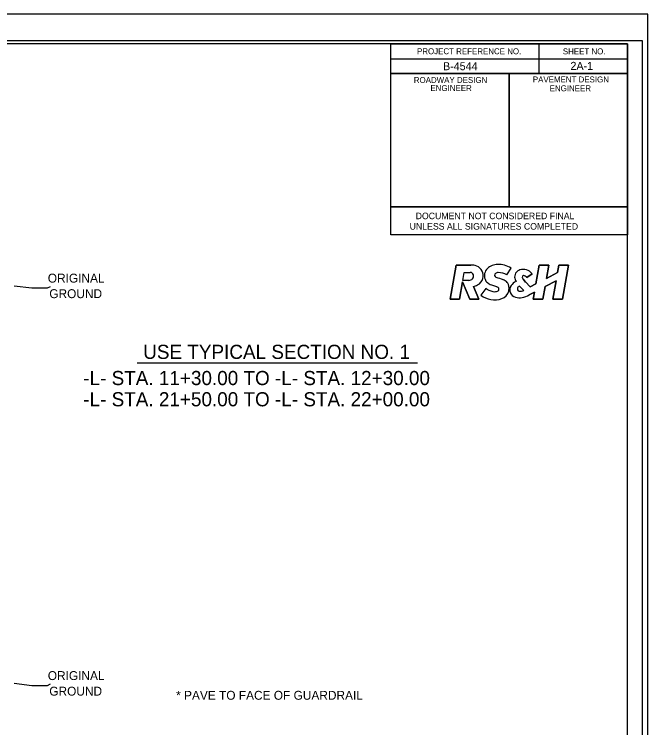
# Model space of a CAD drawing. Extents: x 60664 to 60833, y 51234 to 51344.
# Drawn here: x 60779.3 to 60832.8, y 51284.2 to 51344.4 of the extents above; entities that cross this region are included whole.
import ezdxf

# ---------------------------------------------------------------- set-up
doc = ezdxf.new("R2010")
doc.units = 0
for name, color, linetype in [('Default', 7, 'Continuous'), ('Prop Dimension Text', 7, 'Continuous'), ('Prop DSN Text', 7, 'Continuous'), ('Sheet Cutting Line CELL', 7, 'Continuous'), ('Sheet Data Field CELL', 7, 'Continuous'), ('Sheet Plot Border Inside CELL', 7, 'Continuous'), ('Sheet Plot Border Outside CELL', 7, 'Continuous'), ('Sheet Typical CELL', 7, 'Continuous'), ('Typical Slope Point Local CELL', 7, 'Continuous'), ('Typical Text Label CELL', 7, 'Continuous')]:
    doc.layers.add(name, color=color, linetype=linetype)

msp = doc.modelspace()

# ---------------------------------------------------------------- linework, layer by layer
at = {"layer": 'Default'}
for p, q in [((60816.122, 51320.369), (60816.63, 51323.249)), ((60816.63, 51323.249), (60816.122, 51320.369)), ((60816.63, 51323.249), (60817.88, 51323.249)), ((60817.88, 51323.249), (60816.63, 51323.249)), ((60823.383, 51321.661), (60823.659, 51323.25)), ((60823.659, 51323.25), (60823.383, 51321.661)), ((60823.659, 51323.25), (60824.471, 51323.25)), ((60824.471, 51323.25), (60823.659, 51323.25)), ((60824.471, 51323.25), (60824.273, 51322.128)), ((60824.273, 51322.128), (60824.471, 51323.25)), ((60825.2, 51322.624), (60825.312, 51323.248)), ((60825.312, 51323.248), (60825.2, 51322.624)), ((60825.312, 51323.248), (60826.119, 51323.248)), ((60826.119, 51323.248), (60825.312, 51323.248)), ((60826.119, 51323.248), (60825.616, 51320.364)), ((60825.616, 51320.364), (60826.119, 51323.248)), ((60817.212, 51321.952), (60817.33, 51322.631)), ((60817.212, 51321.952), (60817.33, 51322.631)), ((60817.33, 51322.631), (60817.836, 51322.631)), ((60817.33, 51322.631), (60817.836, 51322.631)), ((60820.918, 51322.42), (60821.28, 51322.999)), ((60824.273, 51322.128), (60825.2, 51322.624)), ((60825.2, 51322.624), (60824.273, 51322.128)), ((60822.323, 51322.03), (60822.511, 51321.814)), ((60822.511, 51321.814), (60822.323, 51322.03)), ((60823.058, 51322.521), (60822.62, 51322.185)), ((60822.62, 51322.185), (60823.058, 51322.521)), ((60817.187, 51321.821), (60816.928, 51320.369)), ((60816.928, 51320.369), (60817.187, 51321.821)), ((60817.789, 51320.363), (60817.187, 51321.821)), ((60817.187, 51321.821), (60817.789, 51320.363)), ((60817.719, 51321.952), (60817.212, 51321.952)), ((60817.719, 51321.952), (60817.212, 51321.952)), ((60818.119, 51321.436), (60818.556, 51320.363)), ((60818.556, 51320.363), (60818.119, 51321.436)), ((60819.615, 51321.577), (60820.058, 51321.426)), ((60822.354, 51321.109), (60821.996, 51321.48)), ((60821.996, 51321.48), (60822.354, 51321.109)), ((60822.506, 51321.821), (60822.896, 51321.408)), ((60822.511, 51321.814), (60822.506, 51321.821)), ((60822.896, 51321.408), (60822.506, 51321.821)), ((60822.506, 51321.821), (60822.511, 51321.814)), ((60822.896, 51321.408), (60823.383, 51321.661)), ((60823.383, 51321.661), (60822.896, 51321.408)), ((60824.149, 51321.44), (60823.963, 51320.364)), ((60823.963, 51320.364), (60824.149, 51321.44)), ((60825.079, 51321.926), (60824.149, 51321.44)), ((60824.149, 51321.44), (60825.079, 51321.926)), ((60824.797, 51320.364), (60825.079, 51321.926)), ((60825.079, 51321.926), (60824.797, 51320.364)), ((60819.148, 51321.267), (60818.717, 51320.707)), ((60819.246, 51321.206), (60819.148, 51321.267)), ((60823.256, 51320.967), (60822.805, 51320.729)), ((60822.805, 51320.729), (60823.256, 51320.967)), ((60823.145, 51320.364), (60823.256, 51320.967)), ((60823.256, 51320.967), (60823.145, 51320.364)), ((60816.928, 51320.369), (60816.122, 51320.369)), ((60816.122, 51320.369), (60816.928, 51320.369)), ((60818.556, 51320.363), (60817.789, 51320.363)), ((60817.789, 51320.363), (60818.556, 51320.363)), ((60823.963, 51320.364), (60823.145, 51320.364)), ((60823.145, 51320.364), (60823.963, 51320.364)), ((60825.616, 51320.364), (60824.797, 51320.364)), ((60824.797, 51320.364), (60825.616, 51320.364))]:
    msp.add_line(p, q, dxfattribs=at)
for centre, radius, start, end in [((60817.88, 51321.816), 1.433, 69.69485, 90), ((60817.88, 51321.816), 1.433, 69.69485, 90), ((60820.164, 51321.865), 1.433, 91.16743, 110.05168), ((60820.179, 51321.123), 2.175, 59.57473, 91.16743), ((60817.836, 51322.365), 0.266, 12.5709, 90), ((60817.836, 51322.365), 0.266, 12.5709, 90), ((60818.082, 51322.361), 0.851, 344.02211, 69.69485), ((60818.082, 51322.361), 0.851, 344.02211, 69.69485), ((60819.89, 51322.349), 0.865, 134.98186, 200.37403), ((60820.043, 51322.196), 1.081, 110.05138, 134.98186), ((60822.14, 51322.271), 0.561, 136.15701, 184.32839), ((60822.14, 51322.271), 0.561, 136.15701, 184.32839), ((60822.222, 51322.192), 0.674, 108.31914, 136.15701), ((60822.222, 51322.192), 0.674, 108.31914, 136.15701), ((60822.311, 51321.924), 0.957, 38.60783, 108.31914), ((60822.311, 51321.924), 0.957, 38.60783, 108.31914), ((60817.719, 51322.338), 0.387, 270, 12.5711), ((60817.719, 51322.338), 0.387, 270, 12.5711), ((60818.021, 51322.379), 0.914, 297.83786, 344.02211), ((60818.021, 51322.379), 0.914, 297.83786, 344.02211), ((60819.707, 51322.28), 0.669, 200.37403, 230.33767), ((60820.061, 51322.402), 0.175, 124.86909, 249.8559), ((60820.193, 51322.213), 0.405, 88.99469, 124.86909), ((60843.623, 51386.635), 68.593, 249.8559, 250.3798), ((60820.174, 51321.123), 1.495, 60.14955, 88.99469), ((60820.301, 51321.213), 0.861, 40.11805, 70.3798), ((60822.434, 51322.293), 0.856, 184.32839, 211.12165), ((60822.434, 51322.293), 0.856, 184.32839, 211.12165), ((60822.361, 51322.226), 0.14, 186.40063, 205.48341), ((60822.361, 51322.226), 0.14, 186.40063, 205.48341), ((60822.777, 51322.424), 0.601, 205.48341, 221.01883), ((60822.777, 51322.424), 0.601, 205.48341, 221.01883), ((60817.613, 51323.152), 1.789, 286.42537, 297.83787), ((60817.613, 51323.152), 1.789, 286.42537, 297.83786), ((60819.961, 51322.587), 1.067, 230.33768, 251.11286), ((60819.908, 51320.986), 0.464, 52.70165, 70.6731), ((60820.547, 51321.421), 0.54, 15.06796, 40.11805), ((60819.947, 51321.259), 1.162, 360, 15.06796), ((60821.827, 51321.16), 0.652, 147.36254, 253.36188), ((60821.827, 51321.16), 0.652, 147.36254, 253.36188), ((60821.991, 51321.055), 0.847, 110.00398, 147.36284), ((60821.991, 51321.055), 0.847, 110.00398, 147.36254), ((60822.129, 51321.176), 0.332, 113.63872, 153.7792), ((60822.129, 51321.176), 0.332, 113.63872, 153.7792), ((60819.968, 51322.373), 1.372, 238.2427, 267.79508), ((60819.932, 51321.442), 0.44, 267.79508, 304.71661), ((60820.086, 51321.22), 0.17, 304.71661, 52.70165), ((60820.214, 51321.266), 0.895, 288.90711, 346.20528), ((60820.242, 51321.259), 0.867, 346.20528, 0), ((60822.007, 51321.236), 0.196, 153.7792, 258.31708), ((60822.007, 51321.236), 0.196, 153.7792, 258.31708), ((60822.077, 51321.571), 0.538, 258.31708, 300.95833), ((60822.077, 51321.571), 0.538, 258.31708, 300.95833), ((60819.881, 51322.239), 1.924, 232.78482, 288.90711), ((60821.97, 51321.638), 1.151, 253.36188, 282.15382), ((60821.97, 51321.638), 1.151, 253.36188, 282.15382), ((60821.725, 51322.775), 2.314, 282.15382, 297.81913), ((60821.725, 51322.775), 2.314, 282.15382, 297.81913)]:
    msp.add_arc(centre, radius, start, end, dxfattribs=at)
msp.add_ellipse((60822.483, 51322.07), major_axis=(0.224, -0.268), ratio=0.514434, start_param=1.570796, end_param=3.802211, dxfattribs=at)
msp.add_ellipse((60822.483, 51322.07), major_axis=(0.224, -0.268), ratio=0.514434, start_param=1.570796, end_param=3.802211, dxfattribs=at)
at = {"layer": 'Prop DSN Text'}
for p, q in [((60811.116, 51325.803), (60811.116, 51328.153)), ((60811.116, 51328.153), (60831.121, 51328.153)), ((60831.121, 51328.152), (60831.121, 51325.802)), ((60831.121, 51325.803), (60811.116, 51325.803))]:
    msp.add_line(p, q, dxfattribs=at)
at = {"layer": 'Sheet Cutting Line CELL'}
msp.add_line((60832.821, 51344.408), (60664.421, 51344.408), dxfattribs=at)
at = {"layer": 'Sheet Plot Border Inside CELL'}
msp.add_lwpolyline([(60832.371, 51342.163), (60665.721, 51342.163), (60665.721, 51236.653), (60832.371, 51236.653)], close=True, dxfattribs=at)
at = {"layer": 'Sheet Plot Border Outside CELL'}
msp.add_lwpolyline([(60832.821, 51344.408), (60664.421, 51344.408), (60664.421, 51234.408), (60832.821, 51234.408)], close=True, dxfattribs=at)
at = {"layer": 'Sheet Typical CELL'}
for p, q in [((60823.621, 51341.903), (60823.621, 51339.403)), ((60811.116, 51340.653), (60831.121, 51340.653)), ((60821.121, 51339.403), (60821.121, 51328.158))]:
    msp.add_line(p, q, dxfattribs=at)
for points in [[(60831.121, 51341.908), (60681.121, 51341.908), (60681.121, 51236.908), (60831.121, 51236.908)], [(60811.116, 51341.908), (60831.121, 51341.908), (60831.121, 51339.403), (60811.116, 51339.403)], [(60811.116, 51339.403), (60821.121, 51339.403), (60821.121, 51328.153), (60811.116, 51328.153)], [(60821.121, 51339.403), (60831.121, 51339.403), (60831.121, 51328.153), (60821.121, 51328.153)]]:
    msp.add_lwpolyline(points, close=True, dxfattribs=at)
at = {"layer": 'Typical Slope Point Local CELL'}
for points in [[(60779.323, 51321.502), (60780.817, 51321.316), (60781.191, 51321.316), (60781.751, 51321.316), (60782.125, 51321.316), (60782.39, 51321.448)], [(60779.323, 51287.965), (60780.817, 51287.779), (60781.191, 51287.779), (60781.751, 51287.779), (60782.125, 51287.779), (60782.39, 51287.911)]]:
    msp.add_lwpolyline(points, dxfattribs=at)
at = {"layer": 'Typical Text Label CELL'}
msp.add_line((60789.702, 51314.99), (60813.382, 51314.99), dxfattribs=at)

# ---------------------------------------------------------------- texts
at = {"layer": 'Prop Dimension Text'}
for s, p in [('ORIGINAL ', (60782.156, 51321.77)), ('GROUND', (60782.282, 51320.458)), ('ORIGINAL ', (60782.156, 51288.234)), ('GROUND', (60782.282, 51286.921)), ('* PAVE TO FACE OF GUARDRAIL ', (60792.994, 51286.572))]:
    msp.add_text(s, height=0.75, dxfattribs=at).set_placement(p)
at = {"layer": 'Prop DSN Text'}
for s, p in [('DOCUMENT NOT CONSIDERED FINAL', (60813.223, 51327.118)), ('UNLESS ALL SIGNATURES COMPLETED', (60812.716, 51326.238))]:
    msp.add_text(s, height=0.55003, dxfattribs=at).set_placement(p)
at = {"layer": 'Sheet Data Field CELL'}
for s, p in [('B-4544', (60815.535, 51339.688)), ('2A-1', (60826.297, 51339.718))]:
    msp.add_text(s, height=0.675, dxfattribs=at).set_placement(p)
at = {"layer": 'Sheet Typical CELL'}
for s, height, p in [('PROJECT REFERENCE NO.', 0.50001, (60813.336, 51341.038)), ('SHEET NO.', 0.5, (60825.651, 51341.028)), ('ROADWAY DESIGN', 0.50001, (60813.066, 51338.613)), ('PAVEMENT DESIGN', 0.50001, (60823.116, 51338.658)), ('ENGINEER', 0.5, (60814.471, 51337.928)), ('ENGINEER', 0.5, (60824.536, 51337.913))]:
    msp.add_text(s, height=height, dxfattribs=at).set_placement(p)
at = {"layer": 'Typical Text Label CELL'}
for s, p in [('USE TYPICAL SECTION NO. 1', (60790.214, 51315.328)), ('-L- STA. 11+30.00 TO -L- STA. 12+30.00 ', (60785.152, 51313.12)), ('-L- STA. 21+50.00 TO -L- STA. 22+00.00', (60785.152, 51311.329))]:
    msp.add_text(s, height=1.19356, dxfattribs=at).set_placement(p)

doc.saveas('drawing.dxf')
